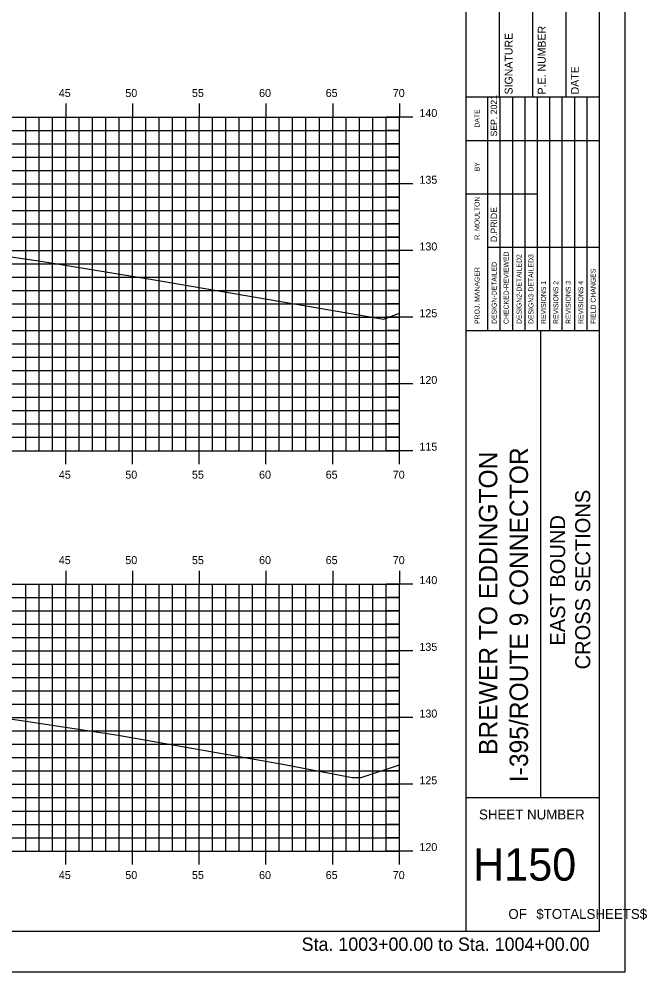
# Model space of a CAD drawing. Extents: x 851073 to 851245, y 365624 to 365734.
# Drawn here: x 851197.8 to 851244.8, y 365624 to 365695.4 of the extents above; entities that cross this region are included whole.
import ezdxf

# ---------------------------------------------------------------- set-up
doc = ezdxf.new("R2010")
doc.units = 0
for name, color, linetype in [('BORDER', 7, 'Continuous'), ('H_V ANNOTATION', 7, 'Continuous'), ('MAJOR', 7, 'Continuous'), ('MINOR', 7, 'Continuous'), ('PLOT BOUNDARY', 7, 'Continuous'), ('S_Roadway_Centerline', 7, 'Continuous')]:
    doc.layers.add(name, color=color, linetype=linetype)

msp = doc.modelspace()

# ---------------------------------------------------------------- linework, layer by layer
at = {"layer": 'BORDER'}
for p, q in [((851231.253, 365627.027), (851231.253, 365732.027)), ((851233.753, 365689.53), (851233.753, 365698.177)), ((851236.253, 365689.53), (851236.253, 365698.177)), ((851238.753, 365689.53), (851238.753, 365698.177)), ((851231.253, 365689.53), (851241.253, 365689.53)), ((851231.253, 365672.03), (851241.253, 365672.03)), ((851236.844, 365637.03), (851236.844, 365672.03)), ((851231.253, 365637.03), (851241.253, 365637.03))]:
    msp.add_line(p, q, dxfattribs=at)
msp.add_lwpolyline([(851081.253, 365627.027), (851241.253, 365627.027), (851241.253, 365732.027), (851081.253, 365732.027)], close=True, dxfattribs=at)
for points in [[(851232.868, 365686.28), (851232.868, 365689.53)], [(851233.8, 365672.033), (851233.8, 365689.53)], [(851234.732, 365689.53), (851234.732, 365672.033)], [(851235.664, 365672.033), (851235.664, 365689.53)], [(851236.595, 365672.033), (851236.595, 365689.53)], [(851237.527, 365672.033), (851237.527, 365689.53)], [(851238.459, 365672.033), (851238.459, 365689.53)], [(851239.39, 365672.033), (851239.39, 365689.53)], [(851240.322, 365672.033), (851240.322, 365689.53)], [(851232.869, 365672.033), (851232.869, 365688.824)], [(851231.253, 365686.28), (851241.253, 365686.28)], [(851231.253, 365682.28), (851232.869, 365682.28)], [(851232.868, 365682.28), (851236.594, 365682.28)], [(851232.868, 365678.28), (851241.253, 365678.28)]]:
    msp.add_lwpolyline(points, dxfattribs=at)
at = {"layer": 'MAJOR'}
for p, q in [((851201.253, 365689.029), (851201.253, 365688.027)), ((851206.253, 365689.029), (851206.253, 365688.027)), ((851211.253, 365689.029), (851211.253, 365688.027)), ((851216.253, 365689.029), (851216.253, 365688.027)), ((851221.253, 365689.029), (851221.253, 365688.027)), ((851226.253, 365689.029), (851226.253, 365688.027)), ((851086.253, 365688.027), (851226.253, 365688.027)), ((851086.253, 365688.027), (851226.253, 365688.027)), ((851201.253, 365663.027), (851201.253, 365688.027)), ((851206.253, 365663.027), (851206.253, 365688.027)), ((851211.253, 365663.027), (851211.253, 365688.027)), ((851216.253, 365663.027), (851216.253, 365688.027)), ((851221.253, 365663.027), (851221.253, 365688.027)), ((851227.255, 365688.027), (851225.251, 365688.027)), ((851226.253, 365663.027), (851226.253, 365688.027)), ((851226.253, 365663.027), (851226.253, 365688.027)), ((851086.253, 365683.027), (851226.253, 365683.027)), ((851227.255, 365683.027), (851225.251, 365683.027)), ((851086.253, 365678.027), (851226.253, 365678.027)), ((851227.255, 365678.027), (851225.251, 365678.027)), ((851086.253, 365673.027), (851226.253, 365673.027)), ((851227.255, 365673.027), (851225.251, 365673.027)), ((851086.253, 365668.027), (851226.253, 365668.027)), ((851227.255, 365668.027), (851225.251, 365668.027)), ((851086.253, 365663.027), (851226.253, 365663.027)), ((851086.253, 365663.027), (851226.253, 365663.027)), ((851201.253, 365662.025), (851201.253, 365663.027)), ((851206.253, 365662.025), (851206.253, 365663.027)), ((851211.253, 365662.025), (851211.253, 365663.027)), ((851216.253, 365662.025), (851216.253, 365663.027)), ((851221.253, 365662.025), (851221.253, 365663.027)), ((851227.255, 365663.027), (851225.251, 365663.027)), ((851226.253, 365662.025), (851226.253, 365663.027)), ((851201.253, 365654.029), (851201.253, 365653.027)), ((851206.253, 365654.029), (851206.253, 365653.027)), ((851211.253, 365654.029), (851211.253, 365653.027)), ((851216.253, 365654.029), (851216.253, 365653.027)), ((851221.253, 365654.029), (851221.253, 365653.027)), ((851226.253, 365654.029), (851226.253, 365653.027)), ((851086.253, 365653.027), (851226.253, 365653.027)), ((851086.253, 365653.027), (851226.253, 365653.027)), ((851201.253, 365633.027), (851201.253, 365653.027)), ((851206.253, 365633.027), (851206.253, 365653.027)), ((851211.253, 365633.027), (851211.253, 365653.027)), ((851216.253, 365633.027), (851216.253, 365653.027)), ((851221.253, 365633.027), (851221.253, 365653.027)), ((851227.255, 365653.027), (851225.251, 365653.027)), ((851226.253, 365633.027), (851226.253, 365653.027)), ((851226.253, 365633.027), (851226.253, 365653.027)), ((851086.253, 365648.027), (851226.253, 365648.027)), ((851227.255, 365648.027), (851225.251, 365648.027)), ((851086.253, 365643.027), (851226.253, 365643.027)), ((851227.255, 365643.027), (851225.251, 365643.027)), ((851086.253, 365638.027), (851226.253, 365638.027)), ((851227.255, 365638.027), (851225.251, 365638.027)), ((851086.253, 365633.027), (851226.253, 365633.027)), ((851086.253, 365633.027), (851226.253, 365633.027)), ((851201.253, 365632.025), (851201.253, 365633.027)), ((851206.253, 365632.025), (851206.253, 365633.027)), ((851211.253, 365632.025), (851211.253, 365633.027)), ((851216.253, 365632.025), (851216.253, 365633.027)), ((851221.253, 365632.025), (851221.253, 365633.027)), ((851227.255, 365633.027), (851225.251, 365633.027)), ((851226.253, 365632.025), (851226.253, 365633.027))]:
    msp.add_line(p, q, dxfattribs=at)
at = {"layer": 'MINOR'}
for p, q in [((851198.253, 365663.027), (851198.253, 365688.027)), ((851199.253, 365663.027), (851199.253, 365688.027)), ((851200.253, 365663.027), (851200.253, 365688.027)), ((851202.253, 365663.027), (851202.253, 365688.027)), ((851203.253, 365663.027), (851203.253, 365688.027)), ((851204.253, 365663.027), (851204.253, 365688.027)), ((851205.253, 365663.027), (851205.253, 365688.027)), ((851207.253, 365663.027), (851207.253, 365688.027)), ((851208.253, 365663.027), (851208.253, 365688.027)), ((851209.253, 365663.027), (851209.253, 365688.027)), ((851210.253, 365663.027), (851210.253, 365688.027)), ((851212.253, 365663.027), (851212.253, 365688.027)), ((851213.253, 365663.027), (851213.253, 365688.027)), ((851214.253, 365663.027), (851214.253, 365688.027)), ((851215.253, 365663.027), (851215.253, 365688.027)), ((851217.253, 365663.027), (851217.253, 365688.027)), ((851218.253, 365663.027), (851218.253, 365688.027)), ((851219.253, 365663.027), (851219.253, 365688.027)), ((851220.253, 365663.027), (851220.253, 365688.027)), ((851222.253, 365663.027), (851222.253, 365688.027)), ((851223.253, 365663.027), (851223.253, 365688.027)), ((851224.253, 365663.027), (851224.253, 365688.027)), ((851225.253, 365663.027), (851225.253, 365688.027)), ((851086.253, 365687.027), (851226.253, 365687.027)), ((851226.253, 365687.027), (851225.251, 365687.027)), ((851086.253, 365686.027), (851226.253, 365686.027)), ((851226.253, 365686.027), (851225.251, 365686.027)), ((851086.253, 365685.027), (851226.253, 365685.027)), ((851226.253, 365685.027), (851225.251, 365685.027)), ((851086.253, 365684.027), (851226.253, 365684.027)), ((851226.253, 365684.027), (851225.251, 365684.027)), ((851086.253, 365682.027), (851226.253, 365682.027)), ((851226.253, 365682.027), (851225.251, 365682.027)), ((851086.253, 365681.027), (851226.253, 365681.027)), ((851226.253, 365681.027), (851225.251, 365681.027)), ((851086.253, 365680.027), (851226.253, 365680.027)), ((851226.253, 365680.027), (851225.251, 365680.027)), ((851086.253, 365679.027), (851226.253, 365679.027)), ((851226.253, 365679.027), (851225.251, 365679.027)), ((851086.253, 365677.027), (851226.253, 365677.027)), ((851226.253, 365677.027), (851225.251, 365677.027)), ((851086.253, 365676.027), (851226.253, 365676.027)), ((851226.253, 365676.027), (851225.251, 365676.027)), ((851086.253, 365675.027), (851226.253, 365675.027)), ((851226.253, 365675.027), (851225.251, 365675.027)), ((851086.253, 365674.027), (851226.253, 365674.027)), ((851226.253, 365674.027), (851225.251, 365674.027)), ((851086.253, 365672.027), (851226.253, 365672.027)), ((851226.253, 365672.027), (851225.251, 365672.027)), ((851086.253, 365671.027), (851226.253, 365671.027)), ((851226.253, 365671.027), (851225.251, 365671.027)), ((851086.253, 365670.027), (851226.253, 365670.027)), ((851226.253, 365670.027), (851225.251, 365670.027)), ((851086.253, 365669.027), (851226.253, 365669.027)), ((851226.253, 365669.027), (851225.251, 365669.027)), ((851086.253, 365667.027), (851226.253, 365667.027)), ((851226.253, 365667.027), (851225.251, 365667.027)), ((851086.253, 365666.027), (851226.253, 365666.027)), ((851226.253, 365666.027), (851225.251, 365666.027)), ((851086.253, 365665.027), (851226.253, 365665.027)), ((851226.253, 365665.027), (851225.251, 365665.027)), ((851086.253, 365664.027), (851226.253, 365664.027)), ((851226.253, 365664.027), (851225.251, 365664.027)), ((851198.253, 365633.027), (851198.253, 365653.027)), ((851199.253, 365633.027), (851199.253, 365653.027)), ((851200.253, 365633.027), (851200.253, 365653.027)), ((851202.253, 365633.027), (851202.253, 365653.027)), ((851203.253, 365633.027), (851203.253, 365653.027)), ((851204.253, 365633.027), (851204.253, 365653.027)), ((851205.253, 365633.027), (851205.253, 365653.027)), ((851207.253, 365633.027), (851207.253, 365653.027)), ((851208.253, 365633.027), (851208.253, 365653.027)), ((851209.253, 365633.027), (851209.253, 365653.027)), ((851210.253, 365633.027), (851210.253, 365653.027)), ((851212.253, 365633.027), (851212.253, 365653.027)), ((851213.253, 365633.027), (851213.253, 365653.027)), ((851214.253, 365633.027), (851214.253, 365653.027)), ((851215.253, 365633.027), (851215.253, 365653.027)), ((851217.253, 365633.027), (851217.253, 365653.027)), ((851218.253, 365633.027), (851218.253, 365653.027)), ((851219.253, 365633.027), (851219.253, 365653.027)), ((851220.253, 365633.027), (851220.253, 365653.027)), ((851222.253, 365633.027), (851222.253, 365653.027)), ((851223.253, 365633.027), (851223.253, 365653.027)), ((851224.253, 365633.027), (851224.253, 365653.027)), ((851225.253, 365633.027), (851225.253, 365653.027)), ((851086.253, 365652.027), (851226.253, 365652.027)), ((851226.253, 365652.027), (851225.251, 365652.027)), ((851086.253, 365651.027), (851226.253, 365651.027)), ((851226.253, 365651.027), (851225.251, 365651.027)), ((851086.253, 365650.027), (851226.253, 365650.027)), ((851226.253, 365650.027), (851225.251, 365650.027)), ((851086.253, 365649.027), (851226.253, 365649.027)), ((851226.253, 365649.027), (851225.251, 365649.027)), ((851086.253, 365647.027), (851226.253, 365647.027)), ((851226.253, 365647.027), (851225.251, 365647.027)), ((851086.253, 365646.027), (851226.253, 365646.027)), ((851226.253, 365646.027), (851225.251, 365646.027)), ((851086.253, 365645.027), (851226.253, 365645.027)), ((851226.253, 365645.027), (851225.251, 365645.027)), ((851086.253, 365644.027), (851226.253, 365644.027)), ((851226.253, 365644.027), (851225.251, 365644.027)), ((851086.253, 365642.027), (851226.253, 365642.027)), ((851226.253, 365642.027), (851225.251, 365642.027)), ((851086.253, 365641.027), (851226.253, 365641.027)), ((851226.253, 365641.027), (851225.251, 365641.027)), ((851086.253, 365640.027), (851226.253, 365640.027)), ((851226.253, 365640.027), (851225.251, 365640.027)), ((851086.253, 365639.027), (851226.253, 365639.027)), ((851226.253, 365639.027), (851225.251, 365639.027)), ((851086.253, 365637.027), (851226.253, 365637.027)), ((851226.253, 365637.027), (851225.251, 365637.027)), ((851086.253, 365636.027), (851226.253, 365636.027)), ((851226.253, 365636.027), (851225.251, 365636.027)), ((851086.253, 365635.027), (851226.253, 365635.027)), ((851226.253, 365635.027), (851225.251, 365635.027)), ((851086.253, 365634.027), (851226.253, 365634.027)), ((851226.253, 365634.027), (851225.251, 365634.027))]:
    msp.add_line(p, q, dxfattribs=at)
at = {"layer": 'PLOT BOUNDARY'}
msp.add_lwpolyline([(851073.159, 365623.968), (851243.159, 365623.968), (851243.159, 365733.968), (851073.159, 365733.968)], close=True, dxfattribs=at)
at = {"layer": 'S_Roadway_Centerline'}
for points in [[(851151.531, 365677.075), (851152.804, 365677.205), (851154.297, 365677.225), (851159.548, 365677.54), (851166.187, 365677.959), (851168.995, 365678.156), (851170.857, 365678.178), (851170.921, 365678.18), (851183.549, 365678.676), (851187.145, 365678.732), (851189.599, 365678.645), (851191.949, 365678.333), (851199.532, 365677.211), (851208.051, 365675.806), (851223.18, 365673.214), (851225.062, 365672.879), (851226.253, 365673.336)], [(851151.044, 365642.279), (851152.802, 365642.489), (851153.315, 365642.683), (851166.611, 365643.347), (851168.344, 365643.455), (851168.666, 365643.558), (851170.94, 365643.653), (851178.594, 365643.862), (851183.609, 365644.018), (851186.36, 365644.087), (851189.184, 365644.011), (851190.428, 365643.857), (851197.751, 365642.835), (851205.186, 365641.722), (851217.642, 365639.516), (851222.712, 365638.535), (851223.393, 365638.547), (851226.253, 365639.478)]]:
    msp.add_lwpolyline(points, dxfattribs=at)

# ---------------------------------------------------------------- texts
at = {"layer": 'BORDER'}
for s, height, p in [('P.E. NUMBER', 0.59055, (851237.214, 365689.722)), ('SIGNATURE', 0.5906, (851234.733, 365689.722)), ('DATE', 0.5906, (851239.694, 365689.722)), ('SEP. 2021', 0.4845, (851233.576, 365686.575)), ('DATE', 0.3714, (851232.257, 365687.235)), ('BY', 0.3714, (851232.257, 365683.965)), ('R. MOULTON', 0.3727, (851232.257, 365678.832)), ('D.PRIDE', 0.4845, (851233.576, 365678.653)), ('CHECKED-REVIEWED', 0.37275, (851234.434, 365672.518)), ('DESIGN-DETAILED', 0.37275, (851233.539, 365672.518)), ('DESIGN2-DETAILED2', 0.37275, (851235.403, 365672.518)), ('DESIGN3-DETAILED3', 0.37275, (851236.297, 365672.518)), ('PROJ. MANAGER', 0.37275, (851232.257, 365672.518)), ('FIELD CHANGES', 0.37275, (851240.956, 365672.518)), ('REVISIONS 1', 0.37275, (851237.229, 365672.518)), ('REVISIONS 2', 0.37275, (851238.16, 365672.518)), ('REVISIONS 3', 0.37275, (851239.092, 365672.518)), ('REVISIONS 4', 0.37275, (851240.024, 365672.518)), ('BREWER TO EDDINGTON', 1.37787, (851233.587, 365640.231)), ('I-395/ROUTE 9 CONNECTOR', 1.37787, (851235.888, 365638.192)), ('CROSS SECTIONS', 1.125, (851240.55, 365646.638)), ('EAST BOUND', 1.125, (851238.671, 365648.418))]:
    msp.add_text(s, height=height, rotation=90, dxfattribs=at).set_placement(p)
for s, height, p in [('SHEET NUMBER', 0.74527, (851232.218, 365635.393)), ('H150', 2.4194, (851231.768, 365630.809)), ('OF', 0.7453, (851234.42, 365627.94)), ('$TOTALSHEETS$', 0.74527, (851236.509, 365627.94))]:
    msp.add_text(s, height=height, dxfattribs=at).set_placement(p)
at = {"layer": 'H_V ANNOTATION'}
for s, height, p in [('45', 0.6, (851200.731, 365689.527)), ('50', 0.6, (851205.717, 365689.527)), ('55', 0.6, (851210.709, 365689.527)), ('60', 0.6, (851215.739, 365689.527)), ('65', 0.6, (851220.731, 365689.527)), ('70', 0.6, (851225.755, 365689.527)), ('140', 0.6, (851227.753, 365688.027)), ('135', 0.6, (851227.753, 365683.027)), ('130', 0.6, (851227.753, 365678.027)), ('125', 0.6, (851227.753, 365673.027)), ('120', 0.6, (851227.753, 365668.027)), ('115', 0.6, (851227.753, 365663.027)), ('45', 0.6, (851200.731, 365660.927)), ('50', 0.6, (851205.717, 365660.927)), ('55', 0.6, (851210.709, 365660.927)), ('60', 0.6, (851215.739, 365660.927)), ('65', 0.6, (851220.731, 365660.927)), ('70', 0.6, (851225.755, 365660.927)), ('45', 0.6, (851200.731, 365654.527)), ('50', 0.6, (851205.717, 365654.527)), ('55', 0.6, (851210.709, 365654.527)), ('60', 0.6, (851215.739, 365654.527)), ('65', 0.6, (851220.731, 365654.527)), ('70', 0.6, (851225.755, 365654.527)), ('140', 0.6, (851227.753, 365653.027)), ('135', 0.6, (851227.753, 365648.027)), ('130', 0.6, (851227.753, 365643.027)), ('125', 0.6, (851227.753, 365638.027)), ('120', 0.6, (851227.753, 365633.027)), ('45', 0.6, (851200.731, 365630.927)), ('50', 0.6, (851205.717, 365630.927)), ('55', 0.6, (851210.709, 365630.927)), ('60', 0.6, (851215.739, 365630.927)), ('65', 0.6, (851220.731, 365630.927)), ('70', 0.6, (851225.755, 365630.927)), ('Sta. 1003+00.00 to Sta. 1004+00.00', 1.0002, (851218.929, 365625.547))]:
    msp.add_text(s, height=height, dxfattribs=at).set_placement(p)

doc.saveas('drawing.dxf')
